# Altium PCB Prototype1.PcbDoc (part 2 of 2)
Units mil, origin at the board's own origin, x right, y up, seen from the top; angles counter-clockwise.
Board outline 2500.51 x 3790.51 mil, 6 copper layers (Signal 1, DGND, +3.3, AGND, +5/+1.2, Signal 4); 76 components, 99 nets, 527 pads, 166 vias.
Unrouted connection lines stored in the file: 15.
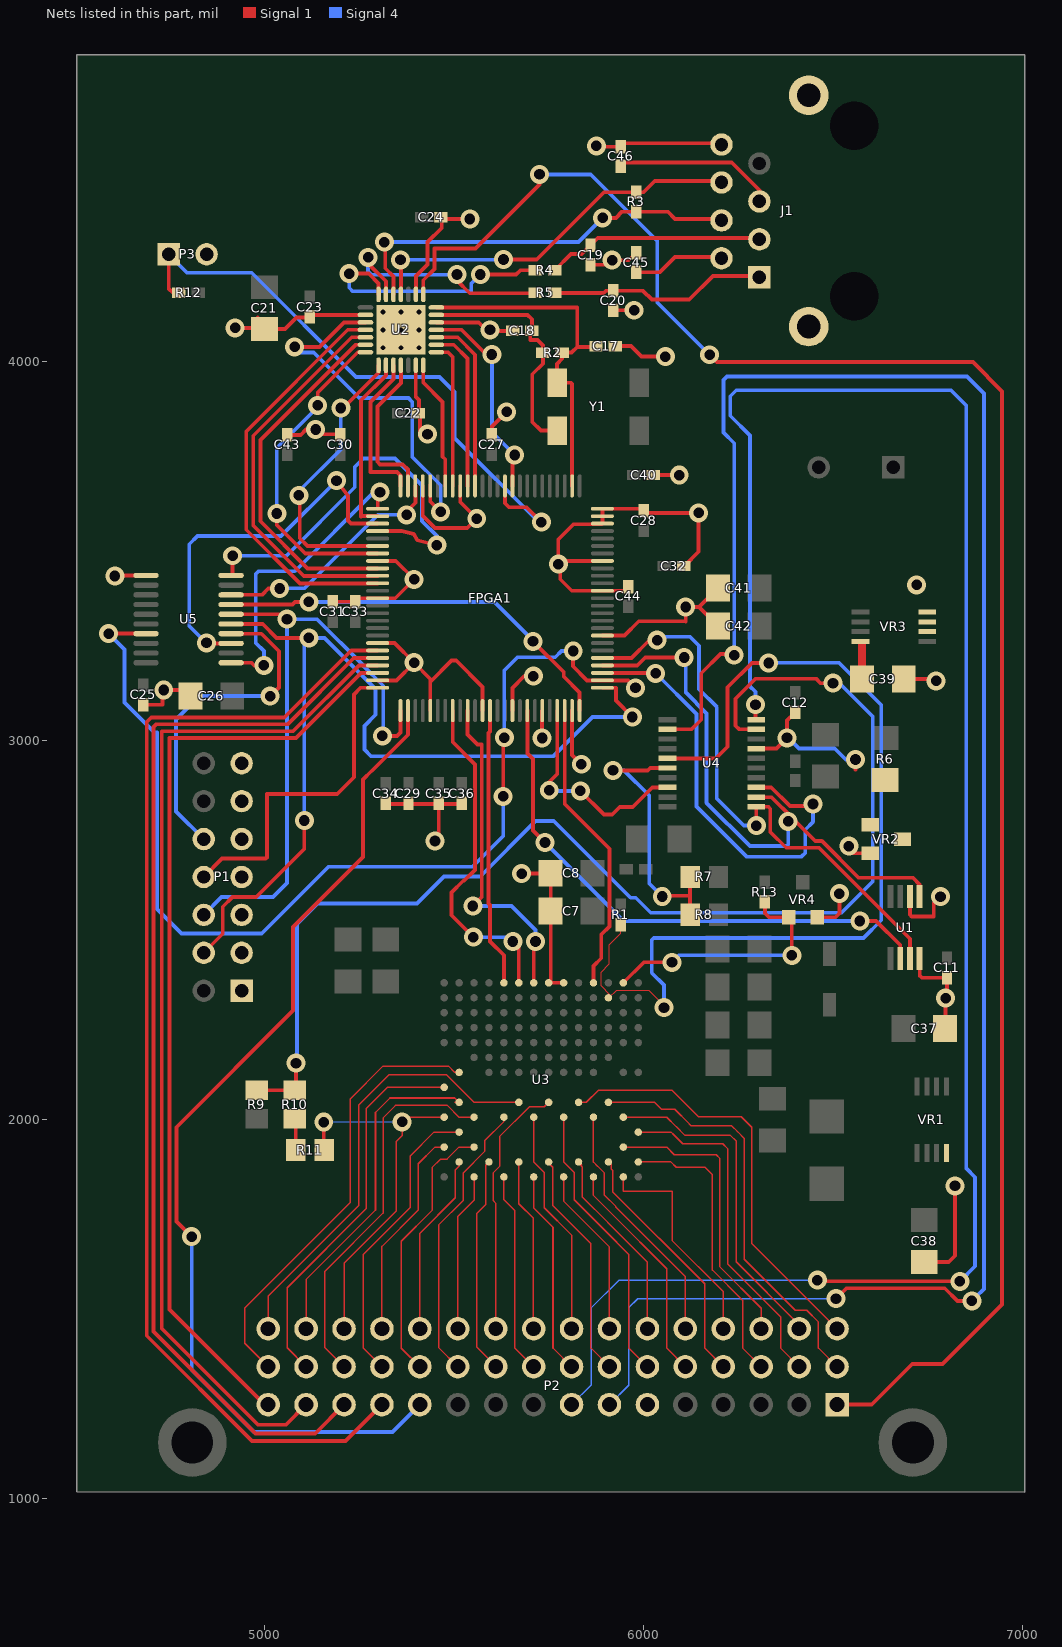
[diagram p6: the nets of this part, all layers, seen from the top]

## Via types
v1: diameter 50, hole 28, Signal 1 to Signal 4, 157 vias
v2: diameter 25.98, hole 12.99, Signal 1 to Signal 4, tented top, 9 vias

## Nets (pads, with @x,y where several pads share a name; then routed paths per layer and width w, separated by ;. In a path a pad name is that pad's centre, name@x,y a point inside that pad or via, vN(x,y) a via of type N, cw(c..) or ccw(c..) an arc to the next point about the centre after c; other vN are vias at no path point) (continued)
AD5535/CATHODE: R1.2 U3.N3 U4.15 | length 2595.2
  Signal 1 w2: U3.N3@5903.5,2321.5 U3.N3@5907.2,2321.5 U3.N3@5907.2,2322.8
  Signal 1 w3: U3.N3@5907.2,2322.8 U3.N3@5910,2322.8 ; R1.2@5940,2514.41 5940,2491.6 5910,2461.6 5910,2410.6 5887.8,2388.4 5887.8,2352.9 5910,2330.7 U3.N3@5910,2322.8 ; v1(6053.7,2295.4) 6053.7,2301.32 6013.61,2341.4 5928.6,2341.4 U3.N3@5910,2322.8
  Signal 1 w10: U4.15@6063.1,2952.6 6190.2,2952.6 6221.2,2983.6 6221.2,3140.09 6285.38,3204.27 v1(6329.63,3204.27)
  Signal 4 w10: v1(6053.7,2295.4) 6053.7,2354.8 6021.3,2387.2 6021.3,2473.7 6026.7,2479.1 6579.7,2479.1 6626.6,2526 6626.6,3093.5 6515.1,3205.01 v1@6330.36,3205.01
AD5535/DGND: C7.1 C8.1 C11.1 C17.2 C18.2 C19.1 C20.2 C21.1 C22.1 C23.1 C24.1 C25.1 C26.1 C27.1 C28.1 C29.1 C30.1 C31.1 C32.1 C33.1 C34.1 C35.1 C36.1 C37.1 C38.1 C39.1 C40.1 C41.1 C42.1 C43.2 C44.1 C45.2 C46.1 FPGA1.8 FPGA1.14 FPGA1.18 FPGA1.23 FPGA1.24 FPGA1.25 FPGA1.42 FPGA1.47 FPGA1.58 FPGA1.63 FPGA1.69 FPGA1.74 FPGA1.80 FPGA1.87 FPGA1.91 FPGA1.95 FPGA1.99 J1.8 J1.MH1 J1.MH2 P1.1 P1.3 P1.5 P1.7 P1.9 P1.11 P1.13 P2.A6 P3.2 U1.4 U1.6 U2.2 U2.9 U2.20 U2.26 U2.29 U3.P6 U3.P7 U5.11 VR1.4 VR2.2 VR3.6 VR3.7 VR3.8 VR4.2 | length 8774.1
  Signal 1 w10: v1(4605.9,3433.7) 4607.36,3435.16 U5.11@4687.8,3435.16 ; C25.1@4680,3094.41 4731.4,3094.41 4731.4,3129.93 v1(4734.67,3133.2) 4788.72,3133.2 C26.1@4804.88,3117.04 ; v1(4922.8,4088) 4996.88,4088 C21.1@5000,4084.88 5054.38,4084.88 5084.74,4115.24 ; C21.1@4970,4102.8 C21.1@4976.05,4108.84 ; C43.2@5060,3805.59 5095.69,3805.59 5110.1,3820 v1(5135,3820) v1@5147.44,3807.56 ; C23.1@5124.37,4122.17 U2.9@5266.5,4122.17 U2.9@5282.04,4122.17 ; C31.1@5180,3365.59 C33.1@5240,3365.59 ; C33.1@5236.75,3368.85 5242.9,3375 FPGA1.63@5298.74,3375 5345,3375 v1(5395,3425) 5346.57,3473.43 FPGA1.58@5298.74,3473.43 ; FPGA1.74@5298.74,3158.46 5348.46,3158.46 v1(5395,3205) ; FPGA1.69@5298.74,3256.89 5343.11,3256.89 ; U2.20@5399.37,3989.29 5399.37,3905.98 5407.56,3897.8 ; U2.2@5399.37,4176.3 5400.15,4177.08 5400.15,4224.75 5430.44,4255.04 5430.44,4314.34 5467.56,4351.46 ; FPGA1.47@5417.83,3671.26 5417.83,3592.17 5450,3560 5535,3560 v1(5560,3585) 5516.26,3628.74 FPGA1.42@5516.26,3671.26 ; FPGA1.80@5437.52,3078.74 5437.52,3154.5 ; v1(5450,2735) v1@5460,2745 ; U2.26@5453.5,4102.48 5565.31,4102.48 5585,4082.8 v1(5595,4082.8) ; C24.1@5472.56,4375 v1(5541.7,4375) ; FPGA1.87@5575.31,3078.74 5575.31,3141.39 5506.1,3210.6 5493.62,3210.6 ; v1@5597.8,4080 C18.2@5654.41,4080 ; C27.1@5600,3805.59 5600,3827.6 v1(5638.8,3866.4) ; FPGA1.91@5654.06,3078.74 5654.06,3138.66 5684.9,3169.5 v1(5709.4,3169.5) ; v1(5678.5,2649) C8.1@5753.88,2649 ; v1(5732.3,3006.6) FPGA1.95@5732.3,3078.24 ; U3.P6@5789.1,2360.9 U3.P7@5749.7,2360.9 U3.P7@5754.88,2366.08 ; FPGA1.99@5811.54,3078.74 5811.54,2961.76 v1(5836,2937.3) ; C19.1@5860,4254.41 5905.11,4254.41 v1(5917.2,4266.5) 5960.91,4266.5 C45.2@5980,4285.59 ; v1(5875.6,4568) 5878.01,4565.59 C46.1@5940,4565.59 5949.41,4575 J1.8@6201.74,4575 ; FPGA1.8@5891.26,3276.57 5949.37,3276.57 5987.2,3314.4 6110.5,3314.4 6110.9,3314 v1(6110.9,3351.8) 6145.78,3351.8 ; FPGA1.18@5891.26,3473.43 5783.43,3473.43 v1(5775,3465) ; C20.2@5920,4134.41 v1(5975.21,4134.41) ; C17.2@5925.59,4040 5967,4040 5994.7,4012.3 v1(6057.1,4012.3) ; C44.1@5960,3405.59 5949.1,3394.69 FPGA1.14@5891.26,3394.69 5810.32,3394.69 5780,3425 5780,3460 v1(5775,3465) ; C40.1@6027.56,3700 6093.5,3700 v1(6094,3699.5) ; C32.1@6107.56,3460 6145,3497.44 v1(6145,3600) C28.1@6007.56,3600 ; C42.1@6195.78,3301.8 6145.78,3351.8 ; C41.1@6195.78,3401.8 6145.78,3351.8 ; VR4.2@6457.4,2533.74 6505.74,2533.74 6516.36,2544.37 v1(6516.36,2595.98) ; v1(6541.3,2721.4) 6541.3,2710.9 6549.6,2702.6 VR2.2@6597.68,2702.6 ; C39.1@6686.02,3161.8 6766.7,3161.8 v1(6771.4,3157.1) ; U1.6@6702.3,2588.19 6702.3,2540.4 6706.8,2535.9 6764.8,2535.9 6764.8,2570.3 v1(6782.8,2588.3) ; U1.4@6727.89,2424.81 6727.89,2380.21 6733.69,2374.41 C11.1@6800,2374.41 6800,2324.2 v1(6796.3,2320.5) ; C38.1@6740,1624.88 6804.78,1624.88 6821,1641.1 v1(6821,1825.6) ; C37.1@6796.3,2241.18 v1(6796.3,2320.5) ; v1@6809.7,2320.5 v1(6796.3,2320.5) ; C21.1@4976.05,4108.84 4982.44,4115.24 C21.1@4976.05,4108.84 ; 5084.74,4115.24 C23.1@5120,4115.24 ; 5084.74,4115.24 C23.1@5120,4115.24 ; 5084.74,4115.24 C23.1@5120,4115.24 ; v1@5147.44,3807.56 C30.1@5200,3807.56 ; v1@5147.44,3807.56 C30.1@5200,3807.56 ; v1@5147.44,3807.56 C30.1@5200,3807.56 ; C34.1@5320,2832.44 C29.1@5380,2832.44 ; C34.1@5320,2832.44 C36.1@5520,2832.44 ; C34.1@5320,2832.44 C35.1@5460,2832.44 ; C34.1@5320,2832.44 C35.1@5460,2832.44 ; C34.1@5320,2832.44 C29.1@5380,2832.44 ; C34.1@5320,2832.44 C29.1@5380,2832.44 ; 5343.11,3256.89 v1(5395,3205) ; 5343.11,3256.89 v1(5395,3205) ; C29.1@5380,2832.44 C35.1@5460,2832.44 ; v1(5395,3205) 5437.52,3162.48 ; v1(5395,3205) 5437.52,3162.48 ; C22.1@5407.56,3862.8 C22.1@5410,3860.35 ; C22.1@5407.56,3862.8 5407.56,3897.8 ; C22.1@5407.56,3862.8 5407.56,3897.8 ; C22.1@5407.56,3862.8 5407.56,3897.8 ; v1@5410,3802.8 v1@5410,3807.8 ; v1@5410,3802.8 C22.1@5410,3860.35 ; v1@5410,3802.8 v1@5410,3807.8 ; v1@5410,3802.8 v1@5410,3807.8 ; v1@5410,3807.8 C22.1@5410,3860.35 ; v1@5410,3807.8 C22.1@5410,3860.35 ; 5437.52,3154.5 5493.62,3210.6 ; 5437.52,3154.5 5493.62,3210.6 ; 5437.52,3154.5 5437.52,3162.48 ; v1@5460,2745 C35.1@5460,2832.44 ; v1@5460,2745 C35.1@5460,2832.44 ; C35.1@5460,2832.44 C36.1@5520,2832.44 ; C35.1@5460,2832.44 C36.1@5520,2832.44 ; 5467.56,4351.46 C24.1@5467.56,4380 ; 5467.56,4351.46 C24.1@5467.56,4380 ; 5467.56,4351.46 C24.1@5467.56,4380 ; C8.1@5753.88,2649 C8.1@5754.88,2648 ; C8.1@5753.88,2649 C8.1@5754.88,2648 ; C8.1@5753.88,2649 C8.1@5754.88,2648 ; U3.P7@5754.88,2366.08 C7.1@5754.88,2550 ; U3.P7@5754.88,2366.08 C7.1@5754.88,2550 ; C7.1@5754.88,2550 C8.1@5754.88,2648 ; v1(5775,3465) 5775,3530 5815.09,3570.09 5889.5,3570.09 FPGA1.23@5891.26,3571.85 FPGA1.24@5891.26,3591.54 FPGA1.25@5891.26,3611.22 C28.1@5996.34,3611.22 ; C28.1@5996.34,3611.22 C28.1@6000.99,3606.58 ; C28.1@5996.34,3611.22 C28.1@6000.99,3606.58 ; C28.1@5996.34,3611.22 C28.1@6000.99,3606.58 ; C28.1@5996.34,3611.22 C28.1@6000.99,3606.58 ; C28.1@5996.34,3611.22 C28.1@6000.99,3606.58 ; C28.1@6000.99,3606.58 C28.1@6007.56,3600 ; C28.1@6000.99,3606.58 C28.1@6007.56,3600 ; C28.1@6000.99,3606.58 C28.1@6007.56,3600 ; C28.1@6000.99,3606.58 C28.1@6007.56,3600 ; C28.1@6000.99,3606.58 C28.1@6007.56,3600
  other v1: 6719.8,3410.5 5430,3807.8
  other v2: 5312.76,4035.55 5360,4035.55 5407.24,4035.55 5312.76,4082.8 5360,4082.8 5407.24,4082.8 5312.76,4130.04 5360,4130.04 5407.24,4130.04
AD5535/DIN: FPGA1.85 U3.P8 | length 879.7
  Signal 1 w10: FPGA1.85@5535.94,3078.74 5535.94,3015.46 5562.2,2989.2 5573.2,2989.2 5573.2,2587.2 v1(5549.6,2563.6) ; U3.P8@5710.3,2360.9 5710.3,2465.3 v1(5715,2470)
  Signal 4 w10: v1(5549.6,2563.6) 5651.6,2563.6 5715,2500.2 v1(5715,2470)
AD5535/REF_IN: R13.2 U3.P2 VR4.3 | length 675
  Signal 1 w2: U3.P2@5946.5,2360.8 U3.P2@5946.5,2360.9
  Signal 1 w10: U3.P2@5946.5,2360.9 6000.6,2415 v1(6075,2415) ; R13.2@6320,2574.41 6320,2544.32 6330.57,2533.74 VR4.3@6382.6,2533.74 6390.68,2525.66 v1(6390.68,2433.53)
  Signal 4 w10: v1(6075,2415) 6093.52,2433.53 v1(6390.68,2433.53)
AD5535/RESET: FPGA1.98 U3.P4 | length 784.3
  Signal 1 w10: FPGA1.98@5791.85,3078.74 5791.85,2832.55 5910,2714.4 5910,2509.5 5888.5,2488 5888.5,2425.6 5867.8,2404.9 U3.P4@5867.8,2360.9
AD5535/SYNC: FPGA1.88 U3.P10 | length 736.1
  Signal 1 w10: FPGA1.88@5595,3078.74 5595,3023.6 5591.2,3019.8 5591.2,2570 5595,2566.2 5595,2470 5631.6,2433.4 U3.P10@5631.6,2360.9
AD7314/CE: FPGA1.93 U1.2 | length 1451.4
  Signal 1 w10: FPGA1.93@5693.43,3078.74 5693.43,2965.47 5708,2950.9 5708,2825 5708,2762.86 v1(5739.94,2730.92) ; v1(6570,2524.01) 6612.99,2524.01 6676.7,2460.3 U1.2@6676.7,2424.81
  Signal 4 w10: v1(5739.94,2730.92) 5946.85,2524.01 6008.99,2524.01 v1(6570,2524.01)
AD7928/CS: FPGA1.3 U4.3 | length 1193.1
  Signal 1 w10: FPGA1.3@5891.26,3178.15 6030.85,3178.15 v1(6031.89,3177.11) ; U4.3@6296.9,2876.2 6336.7,2876.2 6385.9,2827 6441.4,2827 v1(6446.8,2832.4)
  Signal 4 w10: v1(6031.89,3177.11) 6139.1,3069.9 6139.1,2825.5 6271,2693.6 6416.7,2693.6 6426,2702.9 6426,2764.6 6446.8,2785.4 v1(6446.8,2832.4)
AD7928/DOUT: FPGA1.97 U4.18 | length 586.8
  Signal 1 w10: v1(5751.2,2868.7) 5751.2,2890.2 5772.17,2911.17 FPGA1.97@5772.17,3078.74 ; v1(5833,2867.1) 5895.4,2804.7 5917.27,2804.7 5937.27,2824.7 5971.4,2824.7 6022.9,2876.2 U4.18@6063.1,2876.2
  Signal 4 w10: v1(5751.2,2868.7) 5752.8,2867.1 v1(5833,2867.1)
AD7928/REF_IN: C12.2 R6.2 U4.7 VR2.1 | length 400
  Signal 1 w10: U4.7@6296.9,2978.6 6350.1,2978.6 v1(6378.2,3006.7) 6378.2,3052.61 C12.2@6400,3074.41 ; 6558.6,2923.4 v1(6558.6,2949.7)
  Signal 4 w10: v1(6378.2,3006.7) 6382.1,3006.7 6409.9,2978.9 6503.8,2978.9 6533,2949.7 v1(6558.6,2949.7)
AD7928/VHEALTH: R7.1 R8.2 U4.16 | length 754.3
  Signal 1 w10: v1(5919.3,2921.1) 6011.1,2921.1 6017.4,2927.4 U4.16@6063.1,2927.4 ; v1(6049.1,2588.6) 6050.8,2590.3 6122.6,2590.3 6122.6,2560 R7.1@6122.6,2640 R7.1@6122.6,2660
  Signal 4 w10: v1(5919.3,2921.1) 5948.6,2921.1 6015,2854.7 6015,2622.7 v1(6049.1,2588.6)
ADC_EXT1: P2.A7 U4.12 | length 5401.4
  Signal 1 w10: U4.12@6063.1,3029.8 6126.9,3029.8 6151.9,3054.8 6151.9,3177.1 6203.06,3228.26 v1@6235.58,3228.26 ; v1(6507.35,1528.02) 6534.64,1555.31 6794.23,1555.31 6827.41,1522.12 v1(6865.76,1522.12)
  Signal 4 w4: P2.A7@5910,1248.66 5961.06,1299.72 5961.06,1504.58 5984.49,1528.02 v1(6507.35,1528.02)
  Signal 4 w10: v1(6238.92,3224.92) 6238.92,3783.54 6210.34,3812.12 6210.34,3950.17 6220.04,3959.87 6852.37,3959.87 6897.47,3914.77 6897.47,1553.83 6875.72,1532.07 v1@6855.8,1532.07
ADC_EXT2: P2.A8 U4.10 | length 5140.6
  Signal 1 w10: U4.10@6294.97,3056.93 v1(6294.97,3094.39) ; v1(6457.94,1576.69) 6460.89,1573.74 v1(6834.05,1573.74)
  Signal 4 w4: P2.A8@5810,1248.66 5861.34,1300 5861.34,1503.23 5934.8,1576.69 v1(6457.94,1576.69)
  Signal 4 w10: v1@6293.49,3094.39 v1(6294.97,3094.39) 6294.97,3128.31 6280.59,3142.69 6280.59,3804.19 6228.59,3856.18 6228.59,3907.8 6244.08,3923.29 6810.45,3923.29 6851.01,3882.73 6851.01,1870.94 6873.87,1848.08 6873.87,1613.56 v1(6834.05,1573.74)
CLK_5MHZ: FPGA1.5 U1.3 U4.1 | length 1531.5
  Signal 1 w10: FPGA1.5@5891.26,3217.52 5968.22,3217.52 6015,3264.3 v1(6035.8,3264.3) ; v1(6297.2,2775.4) 6296.9,2775.7 U4.1@6296.9,2825 6329,2825 6334,2820 6334,2759 6376.01,2716.99 6462.3,2716.99 6702.3,2477 U1.3@6702.3,2424.81
  Signal 4 w10: v1(6035.8,3264.3) 6045,3273.5 6122.38,3273.5 6146.08,3249.8 6146.08,3134.87 6193.11,3087.83 6193.11,2846.19 6263.9,2775.4 v1(6297.2,2775.4)
CLK_5MHZ_2: FPGA1.83 U3.P9 | length 896.8
  Signal 1 w10: FPGA1.83@5496.57,3078.74 5496.57,2995.53 5555.1,2937 5555.1,2658.5 5526.6,2630 5524.2,2630 5493.4,2599.2 5493.4,2539.1 v1(5551.2,2481.3) ; v1(5655,2470) 5670.9,2454.1 U3.P9@5670.9,2360.9
  Signal 4 w10: v1(5551.2,2481.3) 5643.7,2481.3 v1(5655,2470)
CP2201/AD0: FPGA1.49 U2.18 | length 412.2
  Signal 1 w10: U2.18@5360,3989.29 5360,3942.8 5298,3880.8 5298,3734.8 5305,3727.8 5365,3727.8 5378.46,3714.33 FPGA1.49@5378.46,3671.26
CP2201/AD1: FPGA1.50 U2.17 | length 416.7
  Signal 1 w10: U2.17@5340.32,3989.29 5340.31,3953.11 5280,3892.8 5280,3707.8 5350,3707.8 5358.78,3699.02 FPGA1.50@5358.78,3671.26
CP2201/AD2: FPGA1.52 U2.16 | length 470.9
  Signal 1 w10: FPGA1.52@5298.74,3591.54 5256.54,3591.54 5255,3590 5255,3897.17 5320.63,3962.8 U2.16@5320.63,3989.29
CP2201/AD3: FPGA1.56 U2.15 | length 775.1
  Signal 1 w10: v1(5090.8,3646.5) 5093.14,3644.16 5093.14,3533.34 5113.68,3512.8 FPGA1.56@5298.74,3512.8 ; v1@5201.6,3889.95 v1(5201.6,3876.6) 5207.8,3876.6 5300.94,3969.74 U2.15@5300.94,3989.29
  Signal 4 w10: v1(5090.8,3646.5) 5090.8,3657 5201.6,3767.8 v1(5201.6,3876.6)
CP2201/AD4: FPGA1.57 U2.14 | length 861.2
  Signal 1 w10: v1(5032.68,3598.58) 5032.68,3568.34 5107.91,3493.11 FPGA1.57@5298.74,3493.11 ; v1(5140.6,3883.8) 5140.6,3917.94 5246.4,4023.74 U2.14@5266.5,4023.74
  Signal 4 w10: v1(5032.68,3598.58) 5032.68,3771.48 5140.6,3879.4 v1(5140.6,3883.8)
CP2201/AD5: FPGA1.59 U2.13 | length 956.1
  Signal 1 w10: U2.13@5266.5,4043.43 5240,4043.43 5240,4042.8 4989.6,3792.4 4989.6,3578.2 5114.06,3453.74 FPGA1.59@5298.74,3453.74
CP2201/AD6: FPGA1.60 U2.12 | length 1022.8
  Signal 1 w10: U2.12@5266.5,4063.11 5230.31,4063.11 4970.8,3803.6 4970.8,3567 5103.74,3434.06 FPGA1.60@5298.74,3434.06
CP2201/AD7: FPGA1.61 U2.11 | length 1089.2
  Signal 1 w10: U2.11@5266.5,4082.8 5220,4082.8 4952.3,3815.1 4952.3,3555.5 5094.03,3413.76 FPGA1.61@5298.13,3413.76
CP2201/ALE: FPGA1.44 U2.21 | length 342
  Signal 1 w10: U2.21@5419.06,3989.29 5419.06,3943.74 5470,3892.8 5470,3748.25 5476.89,3741.36 FPGA1.44@5476.89,3671.26
CP2201/CS: FPGA1.40 U2.24 | length 467.1
  Signal 1 w10: U2.24@5453.5,4063.11 5509.69,4063.11 5555.63,4017.17 FPGA1.40@5555.63,3671.26
CP2201/INT: FPGA1.35 U2.25 | length 547.3
  Signal 1 w10: U2.25@5453.5,4082.8 5520,4082.8 5585,4017.8 v1(5600,4017.8) ; FPGA1.35@5654.06,3671.26 5654.06,3746.85 v1(5660,3752.8)
  Signal 4 w10: v1(5600,4017.8) 5600,3812.8 v1(5660,3752.8)
CP2201/LA: P2.A1 U2.1 | length 5026.9
  Signal 1 w10: U2.1@5419.06,4176.3 5419.06,4213.7 5448.44,4243.09 5448.44,4296.89 5556.71,4296.89 5725.44,4465.62 v1(5725.44,4492.61) v1@5709.69,4492.61 ; v1(6174.01,4017.05) 6193.37,3997.68 6868.28,3997.68 6945.41,3920.55 6945.41,1512.53 6788.5,1355.63 6708.58,1355.63 6601.62,1248.66 P2.A1@6510,1248.66
  Signal 4 w10: v1(5725.44,4492.61) 5860.42,4492.61 6035.89,4317.14 6035.89,4155.16 v1(6174.01,4017.05)
CP2201/RD: FPGA1.43 U2.22 | length 388.2
  Signal 1 w10: U2.22@5453.5,4023.74 5484.06,4023.74 5496.57,4011.22 FPGA1.43@5496.57,3671.26
CP2201/RESET: FPGA1.46 U2.10 | length 1095.8
  Signal 1 w10: v1(5080,4037.8) 5145,4037.8 5209.69,4102.48 U2.10@5266.5,4102.48 ; FPGA1.46@5437.52,3674.06 FPGA1.46@5437.52,3671.26 5437.52,3630.28 v1(5465,3602.8)
  Signal 4 w10: v1(5080,4037.8) v1@5080,4022.8 ; v1(5465,3602.8) 5465,3672.8 5390,3747.8 5390,3892.8 5380,3902.8 5250,3902.8 5130,4022.8 ; v1@5080,4022.8 5130,4022.8 ; v1@5080,4022.8 5130,4022.8 ; v1@5080,4022.8 5130,4022.8
CP2201/RX+: J1.4 R3.1 U2.5 | length 1074.6
  Signal 1 w10: v1(5316.2,4314.1) 5318.6,4311.7 5318.6,4245.3 5340.31,4223.59 U2.5@5340.32,4176.3 ; v1(5891.9,4377.9) 5926.8,4377.9 5943.31,4394.41 R3.1@5980,4394.41 6063.43,4394.41 6082.84,4375 J1.4@6201.74,4375
  Signal 4 w10: v1(5316.2,4314.1) 5828.1,4314.1 v1(5891.9,4377.9)
CP2201/RX-: J1.6 R3.2 U2.4 | length 1563.5
  Signal 1 w10: v1(5359,4267.4) 5360,4266.4 U2.4@5360,4176.3 ; v1(5630.4,4268.2) 5718.2,4268.2 5895.59,4445.59 R3.2@5980,4445.59 6000,4445.59 6029.41,4475 J1.6@6201.74,4475
  Signal 4 w10: v1(5630.4,4268.2) v1@5630.4,4267.4 ; v1(5359,4267.4) v1@5630.4,4267.4 ; v1(5359,4267.4) v1@5630.4,4267.4 ; v1(5359,4267.4) v1@5630.4,4267.4
CP2201/TX+: R5.1 U2.6 | length 1077.6
  Signal 1 w10: v1(5273.5,4273.7) 5273.5,4257.96 5320.63,4210.83 U2.6@5320.63,4176.3 ; v1(5507.8,4228.8) 5507.8,4213 5541.5,4179.3 R5.1@5713.71,4179.3
  Signal 4 w10: v1(5273.5,4273.7) 5273.5,4237.4 5283.1,4227.8 ; v1(5507.8,4228.8) v1@5507.8,4227.8 ; 5283.1,4227.8 v1@5507.8,4227.8 ; 5283.1,4227.8 v1@5507.8,4227.8 ; 5283.1,4227.8 v1@5507.8,4227.8
CP2201/TX-: R4.1 U2.7 | length 683.6
  Signal 1 w10: v1(5223.7,4231) 5275,4231 5300.94,4205.06 U2.7@5300.94,4176.3 ; v1(5569.36,4228.56) 5663.86,4228.56 5675.3,4240 R4.1@5714.41,4240
  Signal 4 w10: v1(5223.7,4231) 5223.7,4193.8 5233.2,4184.3 5545.5,4184.3 5545.5,4204.7 v1(5569.36,4228.56)
CP2201/WR: FPGA1.41 U2.23 | length 433.2
  Signal 1 w10: U2.23@5453.5,4043.43 5499.37,4043.43 5535.94,4006.85 FPGA1.41@5535.94,3671.26
CP2201/XTAL2: C18.1 R2.2 U2.27 Y1.1 | length 640.3
  Signal 1 w10: U2.27@5453.5,4122.17 5694.13,4122.17 5705.59,4110.71 C18.1@5705.59,4080 5701.2,4075.61 5701.2,4056.01 5719.89,4056.01 5734.41,4041.49 R2.2@5734.41,4022.8 5734.41,3993.39 5706.5,3965.48 5706.5,3840.1 5729.59,3817.01 Y1.1@5771.73,3817.01
DACHEALTH: R9.1 R10.1 U4.9 | length 3285.8
  Signal 1 w10: R9.1@4980,2077.4 5083.66,2077.4 v1@5083.66,2149.48 ; U4.9@6296.9,3029.8 6251.57,3029.8 6242.58,3038.79 6242.58,3109.78 6295.77,3162.96 6454.35,3162.96 6466.26,3151.06 v1(6499.43,3151.06)
  Signal 4 w10: v1@5081.66,2147.48 5085.92,2151.74 5085.92,2515.74 5140.35,2570.17 5402.3,2570.17 5473.74,2641.62 5568.99,2641.62 5715.28,2787.9 5763,2787.9 5965.8,2585.1 5979.31,2585.1 6018.9,2545.51 6521.54,2545.51 6604.04,2628.01 6604.04,3063.46 v1@6514.74,3152.76
  other v1: 5083.37,2149.18
EEPROM/TDI: P1.10 U5.4 | length 892.3
  Signal 1 w10: U5.4@4912.2,3281.61 4991.99,3281.61 5038.27,3235.33 5038.27,3139.98 v1(5015.33,3117.04)
  Signal 4 w10: P1.10@4840,2740 4766.98,2813.02 4766.98,3054.95 4829.07,3117.04 v1(5015.33,3117.04)
ETH_TX+: C20.1 J1.1 R5.2 | length 573.9
  Signal 1 w10: R5.2@5765.59,4180 5894.41,4180 5900,4185.59 C20.1@5920,4185.59 5998.71,4185.59 6021.8,4162.5 6120.34,4162.5 6182.84,4225 J1.1@6301.74,4225
ETH_TX-: C19.2 J1.3 R4.2 | length 663.6
  Signal 1 w10: R4.2@5765.59,4240 5808.39,4282.8 5836.8,4282.8 ; J1.3@6301.74,4325 5879,4325 ; 5836.8,4282.8 C19.2@5859.8,4305.8 ; 5836.8,4282.8 C19.2@5859.8,4305.8 ; 5836.8,4282.8 C19.2@5859.8,4305.8 ; C19.2@5859.8,4305.8 5879,4325 ; C19.2@5859.8,4305.8 5879,4325
FPGA/CCLK: FPGA1.53 U5.3 | length 1130.1
  Signal 1 w10: v1(4847.4,3257.4) v1@4847.4,3256.02 ; v1(5190,3685) 5220.24,3644.76 5220.24,3579.76 5228.15,3571.85 FPGA1.53@5298.74,3571.85 ; v1@4847.4,3256.02 U5.3@4912.2,3256.02 ; v1@4847.4,3256.02 U5.3@4912.2,3256.02 ; v1@4847.4,3256.02 U5.3@4912.2,3256.02
  Signal 4 w10: v1(4847.4,3257.4) 4846.5,3257.4 4801.7,3302.2 4801.7,3517.5 4823.3,3539.1 5044.1,3539.1 v1(5190,3685)
FPGA/CLK_IN: C17.1 FPGA1.27 R2.1 U2.28 Y1.4 | length 966.7
  Signal 1 w10: U2.28@5453.5,4141.85 5824.06,4141.85 5825,4140.91 5825,4037.8 ; FPGA1.27@5811.54,3671.26 5811.54,3940.74 5809.28,3942.99 Y1.4@5771.73,3942.99 5771.73,3993.13 5785.59,4006.99 R2.1@5785.59,4022.8 5810,4022.8 5825,4037.8 ; C17.1@5874.41,4040 5872.21,4037.8 5825,4037.8
FPGA/DIN: FPGA1.51 U5.1 | length 802.8
  Signal 1 w10: U5.1@4912.2,3204.84 4966.26,3204.84 4973.1,3198 v1(4998.6,3198) ; FPGA1.51@5298.74,3611.22 5298.74,3648.74 v1(5305,3655)
  Signal 4 w10: v1(4998.6,3198) 4998.6,3235.7 4977,3257.3 4977,3438.6 4984.7,3446.3 5080.3,3446.3 5289,3655 v1(5305,3655)
FPGA/DONE: FPGA1.54 U5.10 | length 1061.1
  Signal 1 w10: U5.10@4912.2,3435.16 4916.1,3439.05 v1(4916.1,3487.1) ; FPGA1.54@5298.74,3552.17 5362.17,3552.17 5393.53,3544.19 5403.03,3528.22 v1(5455,3515)
  Signal 4 w10: v1(4916.1,3487.1) 5058.8,3487.9 5238.4,3667.5 5238.4,3720.8 5260.8,3743.2 5344.8,3743.2 5415.8,3672.2 5415.8,3578.1 5455,3538.9 v1(5455,3515)
FPGA/INIT_B: FPGA1.48 U5.8 | length 767.6
  Signal 1 w10: U5.8@4912.2,3383.98 4993.38,3383.98 5010.2,3400.8 v1(5040.2,3400.8) ; v1(5375,3595) 5375,3603.7 5398.15,3626.85 FPGA1.48@5398.15,3671.26
  Signal 4 w10: v1(5040.2,3400.8) v1@5040.2,3401.5 ; v1(5375,3595) 5299.24,3595 5105.74,3401.5 ; v1@5040.2,3401.5 5105.74,3401.5 ; v1@5040.2,3401.5 5105.74,3401.5 ; v1@5040.2,3401.5 5105.74,3401.5
FPGA/PROG_B: FPGA1.100 U5.7 | length 1368.7
  Signal 1 w10: U5.7@4912.2,3358.39 5074.19,3358.39 5081.1,3365.3 v1(5117.3,3365.3) ; v1(5708.2,3261.2) 5789.22,3180.18 5789.22,3168.82 5831.22,3126.82 FPGA1.100@5831.22,3078.74
  Signal 4 w10: v1(5117.3,3365.3) 5606.8,3365.3 ; v1(5708.2,3261.2) v1@5709.55,3262.55 ; 5606.8,3365.3 v1@5709.55,3262.55 ; 5606.8,3365.3 v1@5709.55,3262.55 ; 5606.8,3365.3 v1@5709.55,3262.55
FPGA/TCK: FPGA1.76 P1.6 U5.6 | length 1673
  Signal 1 w10: U5.6@4912.2,3332.8 5046.5,3332.8 v1(5059.5,3319.8) ; v1(5310.9,3012.1) 5350.1,3012.1 5358.78,3020.78 FPGA1.76@5358.78,3078.74
  Signal 4 w10: P1.6@4840,2540 4887.18,2587.18 5022.98,2587.18 5059.5,2623.7 5059.5,3067.8 v1(5059.5,3319.8) 5138.9,3319.8 5260,3198.7 5260,3198 5313.6,3144.4 5313.6,3014.8 v1(5310.9,3012.1)
FPGA/TDI: FPGA1.2 U5.17 | length 2802.9
  Signal 1 w10: v1(4589.35,3281.7) U5.17@4687.71,3281.7 ; v1(5629.8,2852.7) 5629.8,3004.7 v1(5632.6,3007.5) ; v1(5814.5,3236) 5813.6,3238.8 5813.6,3195.63 5850.76,3158.46 5958.84,3158.46 v1(5978.7,3138.6)
  Signal 4 w10: v1(4589.35,3281.7) 4630.97,3240.08 4630.97,3100.06 4710.15,3020.88 4716.81,3020.88 4716.81,2555.72 4781.44,2491.08 4993.21,2491.08 5169.23,2667.1 5548.7,2667.1 5629.8,2748.2 v1(5629.8,2852.7) ; v1(5632.6,3007.5) 5632.6,3184.6 5667.3,3219.3 5767.1,3219.3 5783.8,3236 v1(5814.5,3236)
FPGA/TDO: FPGA1.75 P1.8 | length 891.1
  Signal 1 w10: P1.8@4840,2640 4888.39,2688.39 5003.58,2688.39 5006.9,2691.72 5006.9,2858.6 5192,2858.6 5236.4,2903 5236.4,3121.56 5253.62,3138.78 FPGA1.75@5298.74,3138.78
FPGA/TMS: FPGA1.1 P1.4 U5.5 | length 3463.5
  Signal 1 w10: P1.4@4840,2440 4890.31,2490.31 4890.31,2561.67 4915.82,2587.18 4978.76,2587.18 5105.3,2713.73 v1(5105.3,2788.8) ; U5.5@4912.2,3307.2 4995.5,3307.2 5032.3,3270.4 v1(5117.3,3270.4) ; FPGA1.1@5891.26,3138.78 5927,3138.78 5927,3105 v1(5970.2,3061.8)
  Signal 4 w10: v1(5970.2,3061.8) 5864.9,3061.8 5761.2,2958.1 5281.7,2958.1 5263.9,2975.9 5263.9,3038.4 5293.2,3067.7 5293.2,3135.5 5158.3,3270.4 v1(5117.3,3270.4) v1@5105.3,3270.4 ; v1(5105.3,2788.8) v1@5105.3,3270.4 ; v1(5105.3,2788.8) v1@5105.3,3270.4 ; v1(5105.3,2788.8) v1@5105.3,3270.4
ID0: FPGA1.73 P2.A16 | length 2473.8
  Signal 1 w10: P2.A16@4995.41,1254.2 4749.97,1499.64 4749.97,3006.47 5083.37,3006.47 5255.04,3178.15 FPGA1.73@5298.74,3178.15
ID1: FPGA1.72 P2.A15 | length 2724.3
  Signal 1 w10: P2.A15@5110,1248.66 5056.71,1195.37 4983.38,1195.37 4729.33,1449.42 4729.33,3024.47 5075.85,3024.47 5249.21,3197.83 FPGA1.72@5298.74,3197.83
ID2: FPGA1.71 P2.A14 | length 2905.4
  Signal 1 w10: P2.A14@5210,1248.66 5133.98,1172.64 4976.69,1172.64 4707.94,1441.39 4707.94,3035.88 4714.53,3042.47 5060.68,3042.47 5235.73,3217.52 FPGA1.71@5298.74,3217.52
ID3: FPGA1.70 P2.A13 | length 3080.6
  Signal 1 w10: FPGA1.70@5298.74,3237.2 5229.05,3237.2 5052.32,3060.47 4701.5,3060.47 4689.81,3048.79 4689.81,1430.1 4967.33,1152.58 5213.92,1152.58 P2.A13@5310,1248.66
ID4: FPGA1.77 P2.A12 | length 2707.3
  Signal 1 w10: v1(4808.22,1691.43) 4767.97,1731.68 4767.97,1980.12 5075.64,2287.78 5075.64,2508.4 5260,2692.76 5260,2897.2 5283.1,2920.3 5283.8,2920.3 5378.46,3014.96 FPGA1.77@5378.46,3078.74
  Signal 4 w10: v1(4808.22,1691.43) 4808.22,1341.11 4972.68,1176.65 5337.99,1176.65 P2.A12@5410,1248.66
LM4040/COOL: VR2.3
MASTER_RESET: FPGA1.36 P3.1 R12.2 | length 1634.4
  Signal 1 w10: P3.1@4747.57,4281.99 4747.57,4192 4759.56,4180 R12.2@4774.41,4180 ; FPGA1.36@5634.37,3671.26 5634.37,3625.56 5644.8,3615.12 5691.02,3615.12 v1(5730.32,3575.83)
  Signal 4 w10: P3.1@4744.57,4284.99 4796.15,4233.41 4966.56,4233.41 5241.19,3958.78 5461.6,3958.78 5501.71,3918.67 5501.71,3797.82 5723.7,3575.83 v1(5730.32,3575.83)
NetC45_1: C45.1 J1.2 | length 238.5
  Signal 1 w10: C45.1@5980,4234.41 6042.25,4234.41 6082.84,4275 J1.2@6201.74,4275
NetC46_2: C46.2 J1.5 | length 415.9
  Signal 1 w10: C46.2@5949.3,4524.1 6232.2,4524.1 6305.34,4450.96 J1.5@6305.34,4421.4
NetR10_2: R10.2 R11.1 | length 80
  Signal 1 w10: R11.1@5082.6,1920 R10.2@5082.6,2000
SIPMBIAS0: P2.B3 U3.B1 | length 768.9
  Signal 1 w4: U3.B1@5985.9,1888.5 6029,1888.5 6071.93,1888.5 6085.95,1874.48 6161.78,1874.48 6181.43,1854.83 6181.43,1740.86 6181.43,1603.36 6261.06,1523.74 6261.06,1397.61 P2.B3@6310,1348.66
SIPMBIAS1: P2.C4 U3.A2 | length 584.9
  Signal 1 w4: U3.A2@5946.5,1849.1 5946.5,1811.51 6075.06,1811.51 6075.06,1681.53 6210,1546.59 P2.C4@6210,1448.66
SIPMBIAS2: P2.B2 U3.D1 | length 906.7
  Signal 1 w4: U3.D1@5985.9,1967.2 6072.3,1967.2 6079.3,1960.2 6079.46,1960.2 6103.1,1936.56 6208.56,1936.56 6221.32,1923.8 6221.32,1797.08 6221.32,1619.88 6361.06,1480.15 6361.06,1397.61 P2.B2@6410,1348.66
SIPMBIAS3: P2.C3 U3.C2 | length 761.4
  Signal 1 w4: U3.C2@5946.5,1927.8 6059.3,1927.8 6060.83,1927.8 6080.99,1907.64 6191.55,1907.64 6201.37,1897.82 6201.37,1777.9 6201.37,1611.62 6310,1503 P2.C3@6310,1448.66
SIPMBIAS4: P2.B4 U3.B3 | length 665.3
  Signal 1 w4: U3.B3@5907.2,1888.5 5914.8,1880.9 5914.8,1869.71 5918.7,1865.81 5918.7,1809.68 6161.06,1567.33 6161.06,1397.61 P2.B4@6210,1348.66
SIPMBIAS5: P2.C2 U3.E2 | length 887.2
  Signal 1 w4: U3.E2@5946.5,2006.6 6060.85,2006.6 6085.65,1981.8 ; 6085.79,1981.8 6108.07,1959.52 6228.12,1959.52 6243.99,1943.66 6243.99,1625.41 6410,1459.41 P2.C2@6410,1448.66
SIPMBIAS6: P2.B1 U3.F3 | length 1118.8
  Signal 1 w4: U3.F3@5907.2,2045.9 6028.6,2045.9 6047.2,2027.3 6082.1,2027.3 6119.8,1989.6 6119.8,1989.18 6124.79,1984.19 6216.93,1984.19 6231.67,1984.19 6247.37,1968.49 6265.16,1950.69 6265.16,1820.43 6265.34,1820.25 6265.34,1632.27 6400.01,1497.61 6430.27,1497.61 6461.06,1466.82 6461.06,1397.61 P2.B1@6510,1348.66
SIPMBIAS7: P2.B5 U3.A4 | length 600.8
  Signal 1 w4: U3.A4@5867.8,1849.1 5867.8,1800.2 5917.69,1750.3 6061.06,1606.94 6061.06,1397.61 P2.B5@6110,1348.66
SIPMBIAS8: P2.C5 U3.E4 | length 658.4
  Signal 1 w4: U3.E4@5867.8,2006.6 5867.8,1888.2 5879.1,1876.9 5879.41,1876.89 5895.6,1860.7 5895.6,1860.4 5895.8,1860.2 5895.8,1801.97 5927.05,1770.72 5927.05,1769.15 6110,1586.2 P2.C5@6110,1448.66
SIPMBIAS9: P2.C6 U3.B5 | length 527.1
  Signal 1 w4: 5836.9,1880 U3.B5@5828.4,1888.5 5828.4,1885.52 5837.75,1876.18 5837.75,1797.08 5905.79,1729.04 5905.79,1728.33 6010,1624.12 P2.C6@6010,1448.66
SIPMBIAS10: P2.C1 U3.F5 | length 1135
  Signal 1 w4: U3.F5@5828.4,2045.9 5848.9,2045.9 5880.9,2077.9 6074.6,2077.9 6144.7,2007.8 6257.24,2007.8 6285.1,1979.94 6285.1,1874.47 6285.1,1837.9 6285.28,1837.72 6285.28,1673.38 P2.C1@6510,1448.66
SIPMBIAS11: P2.C7 U3.A6 | length 450.5
  Signal 1 w4: U3.A6@5789.1,1849.1 5789.1,1785.34 5910,1664.44 P2.C7@5910,1448.66
SIPMBIAS12: P2.B6 U3.E6 | length 749.4
  Signal 1 w4: U3.E6@5790,2005.7 5790,1887.51 5816.9,1860.61 5816.9,1789.01 5897.28,1708.63 5961.06,1644.86 5961.06,1397.61 P2.B6@6010,1348.66
  Signal 1 w10: U3.E6@5789.1,2006.6 U3.E6@5790,2005.7
SIPMBIAS13: P2.B7 U3.B7 | length 606.2
  Signal 1 w4: U3.B7@5749.7,1888.5 5749.7,1885.13 5760.35,1874.48 5760.35,1782.62 5760.35,1773.68 5861.06,1672.98 5861.06,1397.61 P2.B7@5910,1348.66
SIPMBIAS14: P2.C10 U3.F7 | length 691.1
  Signal 1 w4: P2.C10@5610.72,1448.66 5610.72,1779.17 5603.8,1786.09 5603.8,1860.7 5620,1876.9 5620,1955.61 5698.79,2034.4 5738.2,2034.4 U3.F7@5749.7,2045.9 U3.F7@5749.7,2053.4
SIPMBIAS15: P2.C8 U3.E8 | length 599.2
  Signal 1 w4: U3.E8@5710.3,2006.6 5710.3,1888.5 5738.1,1860.7 5738.1,1773.41 5738.1,1767.73 5810,1695.83 P2.C8@5810,1448.66
SIPMBIAS16: P2.B8 U3.A8 | length 541.7
  Signal 1 w4: U3.A8@5710.3,1849.1 5710.3,1768.89 5710.3,1767.33 5761.06,1716.57 5761.06,1397.61 P2.B8@5810,1348.66
SIPMBIAS17: P2.C9 U3.B9 | length 455.9
  Signal 1 w4: U3.B9@5670.9,1888.5 5670.9,1778.52 5709.59,1739.83 P2.C9@5709.59,1448.66
SIPMBIAS18: P2.C16 U3.F9 | length 1174.5
  Signal 1 w4: P2.C16@5010,1448.66 5010,1534.72 5248.91,1773.63 5248.91,2038.53 5329.48,2119.1 5479.7,2119.1 5552.9,2045.9 U3.F9@5670.9,2045.9
SIPMBIAS19: P2.B11 U3.E10 | length 750.2
  Signal 1 w4: P2.B11@5510,1348.66 5459.39,1399.28 5459.39,1722.04 5524.1,1786.75 5524.1,1859.71 5580.6,1916.21 5580.6,1944.5 5631.6,1995.5 U3.E10@5631.6,2006.6
SIPMBIAS20: P2.B9 U3.A10 | length 533
  Signal 1 w4: U3.A10@5631.6,1849.1 5631.6,1788.91 5660.12,1760.39 5660.12,1398.28 P2.B9@5709.87,1348.53
SIPMBIAS21: P2.B10 U3.B11 | length 573.1
  Signal 1 w4: U3.B11@5592.2,1888.5 5583.8,1880.1 5583.8,1776.32 5560.17,1752.69 5560.17,1400.72 P2.B10@5611.11,1349.78
SIPMBIAS22: P2.B12 U3.C12 | length 711.8
  Signal 1 w4: P2.B12@5410,1348.66 5361.11,1397.55 5361.11,1679.61 5442.27,1760.78 5442.27,1873.62 5464.85,1896.2 5481.81,1896.2 5513.41,1927.8 U3.C12@5552.8,1927.8
SIPMBIAS23: P2.B13 U3.D13 | length 782.3
  Signal 1 w4: P2.B13@5310,1348.66 5260.83,1397.84 5260.83,1644.48 5384.61,1768.27 5384.61,1904.46 5447.35,1967.2 U3.D13@5513.5,1967.2
SIPMBIAS24: P2.B14 U3.E12 | length 1007
  Signal 1 w4: P2.B14@5210,1348.66 5159.21,1399.45 5159.21,1599.84 5313,1753.63 5313,2004.74 5345.72,2037.46 5482.55,2037.46 5513.41,2006.6 U3.E12@5552.8,2006.6
SIPMBIAS25: P2.C11 U3.A12 | length 418.2
  Signal 1 w4: P2.C11@5510,1448.66 5510,1744.72 5552.8,1787.52 U3.A12@5552.8,1849.1
SIPMBIAS26: P2.C12 U3.B13 | length 481.4
  Signal 1 w4: P2.C12@5410,1450 5410,1700.58 5503.51,1794.09 5503.51,1867.04 5513.5,1877.03 U3.B13@5513.5,1888.5
SIPMBIAS27: P2.B16 U3.H13 | length 1177
  Signal 1 w4: P2.B16@5010,1348.66 4947.94,1410.72 4947.94,1503.57 5226.73,1782.36 5226.73,2055.12 5312.97,2141.37 5485.36,2141.37 5502.03,2124.7 U3.H13@5513.5,2124.7
SIPMBIAS28: P2.B15 U3.G14 | length 1016.3
  Signal 1 w4: P2.B15@5110,1348.66 5060.26,1398.4 5060.26,1557.06 5268.66,1765.45 5268.66,2029.53 5324.43,2085.3 U3.G14@5474.1,2085.3
SIPMBIAS29: P2.C13 U3.C14 | length 561.4
  Signal 1 w4: P2.C13@5310,1448.66 5310,1665.73 5405.9,1761.63 5405.9,1883.98 5449.73,1927.8 U3.C14@5474.1,1927.8
SIPMBIAS30: P2.C15 U3.F13 | length 898.8
  Signal 1 w4: P2.C15@5110,1448.66 5110,1578.56 5293.02,1761.58 5293.02,2019.27 5330.95,2057.2 5502.19,2057.2 U3.F13@5513.5,2045.9 5502.03,2045.9
SIPMBIAS31: P2.C14 R11.2 U3.E14 | length 1004.6
  Signal 1 w4: P2.C14@5210,1448.66 5210,1621.59 5347.74,1759.32 5347.74,1942.14 5363.18,1957.58 v1(5363.18,1994.39) 5375.38,2006.6 U3.E14@5474.1,2006.6
  Signal 1 w10: R11.2@5156.53,1920.87 v1(5156.53,1993.62)
  Signal 4 w4: v1(5156.53,1993.62) v1(5363.18,1994.39)
SPI: FPGA1.4 U1.5 U4.2 | length 1686.9
  Signal 1 w10: FPGA1.4@5891.26,3197.83 5983.23,3197.83 6004.2,3218.8 v1(6106.7,3218.8) ; U4.2@6296.9,2850.2 6337.24,2850.2 ; U1.5@6727.89,2588.19 6727.89,2620.11 6710,2638 6567,2638 6470,2735 6452.44,2735 6400.54,2786.9 v1(6381.2,2786.9) v1@6390.87,2796.57 ; 6337.24,2850.2 v1@6390.87,2796.57 ; 6337.24,2850.2 v1@6390.87,2796.57 ; 6337.24,2850.2 v1@6390.87,2796.57
  Signal 4 w10: v1(6106.7,3218.8) 6111.35,3214.15 6111.35,3126.25 6166.1,3071.5 6166.1,2835.5 6280.2,2721.4 6377.4,2721.4 6381.2,2725.2 v1(6381.2,2786.9)
VR3/SS: C39.2 VR3.4 | length 126.2
  Signal 1 w20: C39.2@6554.44,3183.14 C39.2@6575.78,3161.8 VR3.4@6575.78,3257.82
pads on no net: FPGA1.6 FPGA1.7 FPGA1.9 FPGA1.10 FPGA1.12 FPGA1.13 FPGA1.15 FPGA1.16 FPGA1.19 FPGA1.20 FPGA1.21 FPGA1.28 FPGA1.29 FPGA1.30 FPGA1.31 FPGA1.32 FPGA1.33 FPGA1.34 FPGA1.37 FPGA1.39 FPGA1.62 FPGA1.64 FPGA1.65 FPGA1.78 FPGA1.82 FPGA1.84 FPGA1.86 FPGA1.89 FPGA1.90 FPGA1.94 J1.7 J1.MH3 J1.MH4 P1.12 P1.14 P2.17 P2.18 P2.A9 P2.A10 P2.A11 U1.1 U1.7 U3.A1 U3.A14 U3.P1 U3.P14 U5.2 U5.9 U5.12 U5.13 U5.14 U5.15 U5.16 VR1.5 VR3.2 VR3.5 VR4.1 Y1.2 Y1.3

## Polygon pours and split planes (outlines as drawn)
AD5535/DGND on DGND (split plane): 6985.11,1038.29 4525.38,1039.35 4525.38,4788.01 6985.11,4788.01
+3.3V on +3.3 (split plane): 6985.11,1038.29 4525.38,1039.35 4525.38,4788.01 6985.11,4788.01
AD5535/AGND on AGND (split plane): 6985.11,1038.29 4525.38,1039.35 4525.38,4788.01 6985.11,4788.01
+5V on +5/+1.2 "+5V" (solid, shelved, pour order 1002): 6871.2,1481.2 6842.8,1509.6 6842.8,3956.1 5044.6,3956.1 5039.8,3960.9 5006.7,3927.8 5006.7,1627.9 5006.7,1497.8 5028,1476.5
+1.2V on +5/+1.2 "+1.2V" (solid, shelved, pour order 1001): 6199.2,3230.9 6419.2,3230.9 6484.3,3296 6480.8,3299.5 6480.8,3351.6 6479.6,3351.6 6459.5,3371.7 6453.6,3365.8 6183.8,3365.8
+5V on +5/+1.2 "+5V" (solid, shelved, pour order 1003): 6814.4,1185.4 6842.8,1213.8 6842.8,1624.16 6212.06,1624.16 6173.2,1585.3 6168.5,1580.6 6168.5,1185.4
+1.2V on +5/+1.2 "+1.2V" (solid, shelved, pour order 1000): 6168.5,3059.4 6222.9,3113.8 6222.9,3660.4 6222.9,3700.6 6199.2,3724.3 6142.4,3781.1 5290.6,3781.1 5290.6,3778.6 5252.8,3740.8 5240.9,3728.9 5240.9,3080.7 5240.9,3073.6 5250.4,3064.1 5252.7,3061.8 5281.2,3061.8

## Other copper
Signal 1:
  rectangle net +5V: 6520.6,3328.5 6611.9,3387
  rectangle net +3.3V: 6626.9,1713.3 6774.9,1972.7
  rectangle net AD5535/DGND: 6796.2,1802 6844.7,1980.6
  rectangle net +5V: 6610.7,2157.4 6705.2,2350.9
  rectangle net +5V: 6631.6,2006.7 6777.2,2164.2
  rectangle net LM4040/COOL: 6655,2669.7 6812,2796.2
  rectangle net AD7928/REF_IN: 6576.3,2859.4 6682,2935.8
  rectangle net AD7928/REF_IN: 6547.2,2756.1 6628.8,2935.8
  rectangle net AD5535/DGND: 6653.7,3279.8 6825.5,3474.8
  rectangle net +5V: 6266.9,3358.7 6611.9,3488.7

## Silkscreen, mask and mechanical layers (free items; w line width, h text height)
Top Overlay:
  text "SiPM Digital Control Board" at 4559.52,4703.92 h60
  text "Version 1.0" at 4559.36,4650.41 h30
  text "Designed by UCONN Jones Lab" at 4565.04,4598.47 h30
  text "For USDOE GlueX Experiment" at 4563.7,4546.33 h30
  text "Thomas Jefferson National Laboratory" at 4561.32,4493.9 h30
  text "Newport News, VA" at 4560.16,4446.25 h30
